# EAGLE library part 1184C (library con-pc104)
COMMCON CONNECTOR PC/104
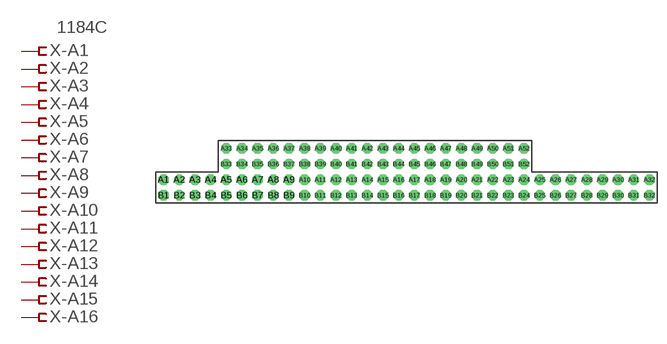
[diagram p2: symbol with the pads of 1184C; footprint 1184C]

Designator prefix X; gates -A1=PIN-V -A2=PIN-B -A3=PIN-B -A4=PIN-B -A5=PIN-B -A6=PIN-B -A7=PIN-B -A8=PIN-B -A9=PIN-B -A10=PIN-B -A11=PIN-B -A12=PIN-B -A13=PIN-B -A14=PIN-B -A15=PIN-B -A16=PIN-B -A17=PIN-B -A18=PIN-B -A19=PIN-B -A20=PIN-B -A21=PIN-B -A22=PIN-B -A23=PIN-B -A24=PIN-B -A25=PIN-B -A26=PIN-B -A27=PIN-B -A28=PIN-B -A29=PIN-B -A30=PIN-B -A31=PIN-B -A32=PIN-B -B1=PIN-V -B2=PIN-B -B3=PIN-B -B4=PIN-B -B5=PIN-B -B6=PIN-B -B7=PIN-B -B8=PIN-B -B9=PIN-B -B10=PIN-B -B11=PIN-B -B12=PIN-B -B13=PIN-B -B14=PIN-B -B15=PIN-B -B16=PIN-B -B17=PIN-B -B18=PIN-B -B19=PIN-B -B20=PIN-B -B21=PIN-B -B22=PIN-B -B23=PIN-B -B24=PIN-B -B25=PIN-B -B26=PIN-B -B27=PIN-B -B28=PIN-B -B29=PIN-B -B30=PIN-B -B31=PIN-B -B32=PIN-B -A33=PIN-B -A34=PIN-B -A35=PIN-B -A36=PIN-B -A37=PIN-B -A38=PIN-B -A39=PIN-B -A40=PIN-B -A41=PIN-B -A42=PIN-B -A43=PIN-B -A44=PIN-B -A45=PIN-B -A46=PIN-B -A47=PIN-B -A48=PIN-B -A49=PIN-B -A50=PIN-B -A51=PIN-B -A52=PIN-B -B33=PIN-B -B34=PIN-B -B35=PIN-B -B36=PIN-B -B37=PIN-B -B38=PIN-B -B39=PIN-B -B40=PIN-B -B41=PIN-B -B42=PIN-B -B43=PIN-B -B44=PIN-B -B45=PIN-B -B46=PIN-B -B47=PIN-B -B48=PIN-B -B49=PIN-B -B50=PIN-B -B51=PIN-B -B52=PIN-B

## 1184C  [1184C]
A1  -A1:1  pas
A2  -A2:1  pas
A3  -A3:1  pas
A4  -A4:1  pas
A5  -A5:1  pas
A6  -A6:1  pas
A7  -A7:1  pas
A8  -A8:1  pas
A9  -A9:1  pas
A10  -A10:1  pas
A11  -A11:1  pas
A12  -A12:1  pas
A13  -A13:1  pas
A14  -A14:1  pas
A15  -A15:1  pas
A16  -A16:1  pas
A17  -A17:1  pas
A18  -A18:1  pas
A19  -A19:1  pas
A20  -A20:1  pas
A21  -A21:1  pas
A22  -A22:1  pas
A23  -A23:1  pas
A24  -A24:1  pas
A25  -A25:1  pas
A26  -A26:1  pas
A27  -A27:1  pas
A28  -A28:1  pas
A29  -A29:1  pas
A30  -A30:1  pas
A31  -A31:1  pas
A32  -A32:1  pas
A33  -A33:1  pas
A34  -A34:1  pas
A35  -A35:1  pas
A36  -A36:1  pas
A37  -A37:1  pas
A38  -A38:1  pas
A39  -A39:1  pas
A40  -A40:1  pas
A41  -A41:1  pas
A42  -A42:1  pas
A43  -A43:1  pas
A44  -A44:1  pas
A45  -A45:1  pas
A46  -A46:1  pas
A47  -A47:1  pas
A48  -A48:1  pas
A49  -A49:1  pas
A50  -A50:1  pas
A51  -A51:1  pas
A52  -A52:1  pas
B1  -B1:1  pas
B2  -B2:1  pas
B3  -B3:1  pas
B4  -B4:1  pas
B5  -B5:1  pas
B6  -B6:1  pas
B7  -B7:1  pas
B8  -B8:1  pas
B9  -B9:1  pas
B10  -B10:1  pas
B11  -B11:1  pas
B12  -B12:1  pas
B13  -B13:1  pas
B14  -B14:1  pas
B15  -B15:1  pas
B16  -B16:1  pas
B17  -B17:1  pas
B18  -B18:1  pas
B19  -B19:1  pas
B20  -B20:1  pas
B21  -B21:1  pas
B22  -B22:1  pas
B23  -B23:1  pas
B24  -B24:1  pas
B25  -B25:1  pas
B26  -B26:1  pas
B27  -B27:1  pas
B28  -B28:1  pas
B29  -B29:1  pas
B30  -B30:1  pas
B31  -B31:1  pas
B32  -B32:1  pas
B33  -B33:1  pas
B34  -B34:1  pas
B35  -B35:1  pas
B36  -B36:1  pas
B37  -B37:1  pas
B38  -B38:1  pas
B39  -B39:1  pas
B40  -B40:1  pas
B41  -B41:1  pas
B42  -B42:1  pas
B43  -B43:1  pas
B44  -B44:1  pas
B45  -B45:1  pas
B46  -B46:1  pas
B47  -B47:1  pas
B48  -B48:1  pas
B49  -B49:1  pas
B50  -B50:1  pas
B51  -B51:1  pas
B52  -B52:1  pas

## Footprint 1184C (pad centres in mm)
COMMCON CONNECTOR PC/104
drill 1.118 octagon: A1 -39.37,-1.27; A2 -36.83,-1.27; A3 -34.29,-1.27; A4 -31.75,-1.27; A5 -29.21,-1.27; A6 -26.67,-1.27; A7 -24.13,-1.27; A8 -21.59,-1.27; A9 -19.05,-1.27; A10 -16.51,-1.27; A11 -13.97,-1.27; A12 -11.43,-1.27; A13 -8.89,-1.27; A14 -6.35,-1.27; A15 -3.81,-1.27; A16 -1.27,-1.27; A17 1.27,-1.27; A18 3.81,-1.27; A19 6.35,-1.27; A20 8.89,-1.27; A21 11.43,-1.27; A22 13.97,-1.27; A23 16.51,-1.27; A24 19.05,-1.27; A25 21.59,-1.27; A26 24.13,-1.27; A27 26.67,-1.27; A28 29.21,-1.27; A29 31.75,-1.27; A30 34.29,-1.27; A31 36.83,-1.27; A32 39.37,-1.27; A33 -29.21,3.81; A34 -26.67,3.81; A35 -24.13,3.81; A36 -21.59,3.81; A37 -19.05,3.81; A38 -16.51,3.81; A39 -13.97,3.81; A40 -11.43,3.81; A41 -8.89,3.81; A42 -6.35,3.81; A43 -3.81,3.81; A44 -1.27,3.81; A45 1.27,3.81; A46 3.81,3.81; A47 6.35,3.81; A48 8.89,3.81; A49 11.43,3.81; A50 13.97,3.81; A51 16.51,3.81; A52 19.05,3.81; B1 -39.37,-3.81; B2 -36.83,-3.81; B3 -34.29,-3.81; B4 -31.75,-3.81; B5 -29.21,-3.81; B6 -26.67,-3.81; B7 -24.13,-3.81; B8 -21.59,-3.81; B9 -19.05,-3.81; B10 -16.51,-3.81; B11 -13.97,-3.81; B12 -11.43,-3.81; B13 -8.89,-3.81; B14 -6.35,-3.81; B15 -3.81,-3.81; B16 -1.27,-3.81; B17 1.27,-3.81; B18 3.81,-3.81; B19 6.35,-3.81; B20 8.89,-3.81; B21 11.43,-3.81; B22 13.97,-3.81; B23 16.51,-3.81; B24 19.05,-3.81; B25 21.59,-3.81; B26 24.13,-3.81; B27 26.67,-3.81; B28 29.21,-3.81; B29 31.75,-3.81; B30 34.29,-3.81; B31 36.83,-3.81; B32 39.37,-3.81; B33 -29.21,1.27; B34 -26.67,1.27; B35 -24.13,1.27; B36 -21.59,1.27; B37 -19.05,1.27; B38 -16.51,1.27; B39 -13.97,1.27; B40 -11.43,1.27; B41 -8.89,1.27; B42 -6.35,1.27; B43 -3.81,1.27; B44 -1.27,1.27; B45 1.27,1.27; B46 3.81,1.27; B47 6.35,1.27; B48 8.89,1.27; B49 11.43,1.27; B50 13.97,1.27; B51 16.51,1.27; B52 19.05,1.27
